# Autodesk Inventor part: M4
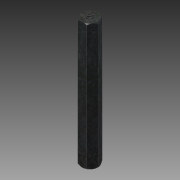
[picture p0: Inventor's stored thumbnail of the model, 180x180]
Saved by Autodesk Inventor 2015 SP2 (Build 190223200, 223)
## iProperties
Created: 2012-08
Part Number: M4
Material: Stahl
Document SubType Name: Modeling
Designer: rYan
Mass: 3.36246 g
Surface Area: 5.74911 cm^2
Volume: 0.428339 cm^3
Density: 7.85 g/cm^3
Appearance: Platte
Author: rYan
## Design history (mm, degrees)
derived "Abstandsbolzen Typ A.ipt"
feature "Volumenkörper1::Abstandsbolzen Typ A.ipt"
tag "Bezeichnung1"
node "Volumenkörper1"
other parameters: "SW" = 8, "L" = 65, "d2" = 0, "d16" = 45 deg
